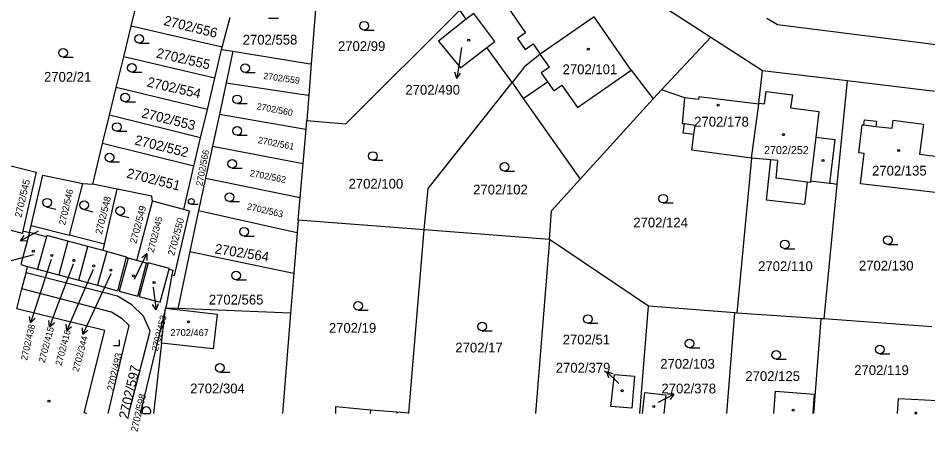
# Model space of a CAD drawing. Extents: x -496682 to -495776, y -1088797 to -1088018.
# Drawn here: x -496557.4 to -496399.5, y -1088572.6 to -1088500.7 of the extents above; entities that cross this region are included whole.
import ezdxf

# ---------------------------------------------------------------- set-up
doc = ezdxf.new("R2010")
doc.units = 0
for name, color, linetype in [('Hranice parcel', 7, 'Continuous'), ('Parcelní čísla', 7, 'Continuous'), ('Pop  PČ popisy', 7, 'Continuous'), ('Vnitřní kresba', 7, 'Continuous'), ('Značky budov', 7, 'Continuous'), ('Značky kultur', 7, 'Continuous')]:
    doc.layers.add(name, color=color, linetype=linetype)

msp = doc.modelspace()

# ---------------------------------------------------------------- linework, layer by layer
at = {"layer": 'Hranice parcel'}
for p, q in [((-496537.8, -1088502.11), (-496536.46, -1088496.6)), ((-496450.23, -1088495.49), (-496437.15, -1088504)), ((-496505.72, -1088498.45), (-496506.52, -1088508.66)), ((-496479.61, -1088500.91), (-496480.76, -1088499.32)), ((-496522.01, -1088505.76), (-496520.6, -1088500.55)), ((-496539.1, -1088507.43), (-496537.8, -1088502.11)), ((-496522.01, -1088505.76), (-496537.8, -1088502.11)), ((-496445.71, -1088513.16), (-496437.15, -1088504)), ((-496437.15, -1088504), (-496428.21, -1088509.82)), ((-496523.29, -1088511.13), (-496522.11, -1088506.13)), ((-496522.11, -1088506.13), (-496522.01, -1088505.76)), ((-496522.11, -1088506.13), (-496520.16, -1088506.45)), ((-496471.67, -1088511.91), (-496476.06, -1088505.83)), ((-496540.39, -1088512.75), (-496539.1, -1088507.43)), ((-496523.29, -1088511.13), (-496539.1, -1088507.43)), ((-496520.16, -1088506.45), (-496521.33, -1088511.93)), ((-496506.52, -1088508.66), (-496506.95, -1088514.12)), ((-496469.49, -1088509.17), (-496471.67, -1088511.91)), ((-496428.21, -1088509.82), (-496413.5, -1088511.53)), ((-496524.57, -1088516.56), (-496523.29, -1088511.13)), ((-496521.33, -1088511.93), (-496522.49, -1088517.38)), ((-496413.5, -1088511.53), (-496415.26, -1088529.6)), ((-496413.5, -1088511.53), (-496394.97, -1088513.78)), ((-496541.56, -1088517.57), (-496540.39, -1088512.75)), ((-496524.57, -1088516.56), (-496540.39, -1088512.75)), ((-496506.95, -1088514.12), (-496507.29, -1088518.51)), ((-496441.68, -1088514.55), (-496445.71, -1088513.16)), ((-496525.75, -1088521.53), (-496524.57, -1088516.56)), ((-496522.49, -1088517.38), (-496523.68, -1088522.94)), ((-496542.77, -1088522.52), (-496541.56, -1088517.57)), ((-496525.75, -1088521.53), (-496541.56, -1088517.57)), ((-496507.42, -1088520.02), (-496507.29, -1088518.51)), ((-496507.95, -1088525.99), (-496507.42, -1088520.02)), ((-496526.9, -1088526.44), (-496525.75, -1088521.53)), ((-496544.48, -1088529.55), (-496542.77, -1088522.52)), ((-496526.9, -1088526.44), (-496542.77, -1088522.52)), ((-496523.68, -1088522.94), (-496524.87, -1088528.52)), ((-496523.68, -1088522.94), (-496507.95, -1088525.99)), ((-496430.07, -1088525.02), (-496432.62, -1088551.99)), ((-496528.68, -1088533.96), (-496526.9, -1088526.44)), ((-496508.46, -1088531.91), (-496507.95, -1088525.99)), ((-496548.52, -1088538.44), (-496546.2, -1088529.44)), ((-496546.2, -1088529.44), (-496544.48, -1088529.55)), ((-496540.23, -1088530.42), (-496544.48, -1088529.55)), ((-496524.87, -1088528.52), (-496526.08, -1088534.17)), ((-496524.87, -1088528.52), (-496508.46, -1088531.91)), ((-496415.26, -1088529.6), (-496417.53, -1088552.98)), ((-496542.41, -1088540.01), (-496540.23, -1088530.42)), ((-496536.84, -1088542.85), (-496534.08, -1088532.5)), ((-496528.68, -1088533.96), (-496534.08, -1088532.5)), ((-496508.81, -1088535.85), (-496508.46, -1088531.91)), ((-496526.08, -1088534.17), (-496527.6, -1088541.29)), ((-496508.81, -1088535.85), (-496508.98, -1088537.97)), ((-496486.91, -1088537.52), (-496508.81, -1088535.85)), ((-496556.58, -1088537.69), (-496555.46, -1088537.96)), ((-496555.46, -1088537.96), (-496555.17, -1088536.73)), ((-496555.17, -1088536.73), (-496548.52, -1088538.44)), ((-496489.6, -1088569.29), (-496486.91, -1088537.52)), ((-496465.19, -1088539.18), (-496486.91, -1088537.52)), ((-496552.5, -1088538.74), (-496555.46, -1088537.96)), ((-496552.5, -1088538.74), (-496554.06, -1088544.33)), ((-496548.78, -1088539.48), (-496550.36, -1088545.33)), ((-496545.3, -1088540.41), (-496548.78, -1088539.48)), ((-496542.41, -1088540.01), (-496548.52, -1088538.44)), ((-496508.98, -1088537.97), (-496509.56, -1088545.05)), ((-496465.19, -1088539.18), (-496467.58, -1088569.45)), ((-496447.96, -1088550.78), (-496465.19, -1088539.18)), ((-496546.88, -1088546.28), (-496545.3, -1088540.41)), ((-496542.66, -1088541.12), (-496545.3, -1088540.41)), ((-496542.66, -1088541.12), (-496542.41, -1088540.01)), ((-496542.04, -1088541.29), (-496543.64, -1088547.15)), ((-496542.04, -1088541.29), (-496542.66, -1088541.12)), ((-496538.59, -1088542.23), (-496542.04, -1088541.29)), ((-496538.59, -1088542.23), (-496538.33, -1088542.45)), ((-496536.84, -1088542.85), (-496538.33, -1088542.45)), ((-496556.05, -1088544.98), (-496555.77, -1088543.87)), ((-496555.77, -1088543.87), (-496554.06, -1088544.33)), ((-496535.12, -1088543.32), (-496536.84, -1088542.85)), ((-496535.12, -1088543.32), (-496534.84, -1088543.23)), ((-496556.76, -1088547.74), (-496556.05, -1088544.98)), ((-496554.06, -1088544.33), (-496550.36, -1088545.33)), ((-496550.36, -1088545.33), (-496546.88, -1088546.28)), ((-496509.56, -1088545.05), (-496510.13, -1088551.97)), ((-496546.88, -1088546.28), (-496543.64, -1088547.15)), ((-496557.65, -1088551.23), (-496556.76, -1088547.74)), ((-496531.82, -1088551.13), (-496536.21, -1088569.45)), ((-496532.51, -1088557.18), (-496531.82, -1088551.13)), ((-496529.72, -1088551.21), (-496531.82, -1088551.13)), ((-496510.13, -1088551.97), (-496529.72, -1088551.21)), ((-496449.5, -1088569.45), (-496447.96, -1088550.78)), ((-496433, -1088551.96), (-496447.96, -1088550.78)), ((-496434.4, -1088569.45), (-496433, -1088551.96)), ((-496432.62, -1088551.99), (-496433, -1088551.96)), ((-496418.06, -1088552.96), (-496432.62, -1088551.99)), ((-496418.06, -1088552.96), (-496419.34, -1088569.45)), ((-496417.53, -1088552.98), (-496418.06, -1088552.96)), ((-496398.8, -1088554.34), (-496417.53, -1088552.98)), ((-496532.51, -1088557.18), (-496533.9, -1088569.45)), ((-496489.61, -1088569.45), (-496489.6, -1088569.29))]:
    msp.add_line(p, q, dxfattribs=at)
for points in [[(-496507.29, -1088518.51), (-496500.51, -1088519.07), (-496480.76, -1088499.32)], [(-496476.06, -1088505.83), (-496474.64, -1088504.74), (-496478.32, -1088499.89), (-496479.61, -1088500.91)], [(-496479.61, -1088500.91), (-496484.42, -1088504.69), (-496480.61, -1088509.32), (-496476.06, -1088505.83)], [(-496457.42, -1088500.49), (-496466.76, -1088506.96), (-496469.49, -1088509.17)], [(-496465.53, -1088511.75), (-496464.43, -1088513.34), (-496463.02, -1088512.35), (-496460.32, -1088516.24), (-496450.98, -1088509.77), (-496457.42, -1088500.49)], [(-496427.43, -1088500.69), (-496425.57, -1088501.8), (-496381.96, -1088507.33)], [(-496520.16, -1088506.45), (-496507.08, -1088508.57), (-496506.52, -1088508.66)], [(-496430.07, -1088525.02), (-496428.84, -1088515.66), (-496428.82, -1088515.46), (-496428.21, -1088509.82)], [(-496521.33, -1088511.93), (-496508.27, -1088513.92), (-496506.95, -1088514.12)], [(-496486.91, -1088537.52), (-496486.26, -1088530.32), (-496471.67, -1088511.91)], [(-496471.67, -1088511.91), (-496469.73, -1088514.66), (-496465.53, -1088511.75)], [(-496465.19, -1088539.18), (-496464.79, -1088534.19), (-496459.83, -1088528.71), (-496447.17, -1088514.73), (-496445.71, -1088513.16)], [(-496430.07, -1088525.02), (-496440.44, -1088523.65), (-496440.09, -1088520.95), (-496441.94, -1088520.7), (-496441.73, -1088519.1), (-496442.06, -1088519.05), (-496441.68, -1088514.55)], [(-496522.49, -1088517.38), (-496507.83, -1088519.95), (-496507.42, -1088520.02)], [(-496401.7, -1088530.59), (-496411.17, -1088529.49), (-496410.56, -1088524.24), (-496411.46, -1088524.14), (-496410.89, -1088519.24), (-496410.59, -1088519.28), (-496410.48, -1088518.4), (-496408.38, -1088518.63), (-496408.48, -1088519.52), (-496405.68, -1088519.85), (-496405.48, -1088518.47), (-496400.24, -1088519.14), (-496400.91, -1088524.37), (-496396.87, -1088524.88), (-496397.69, -1088531.06), (-496401.7, -1088530.59)], [(-496415.26, -1088529.6), (-496416.28, -1088529.48), (-496416.53, -1088529.45), (-496419.84, -1088529.05), (-496419.87, -1088529.29), (-496420.45, -1088529.21), (-496420.88, -1088533.09), (-496427.49, -1088532.36), (-496426.73, -1088525.36), (-496430.07, -1088525.02)], [(-496560.1, -1088526.02), (-496554.29, -1088527.46), (-496556.58, -1088537.69)], [(-496555.17, -1088536.73), (-496553.11, -1088528.01), (-496546.2, -1088529.44)], [(-496534.08, -1088532.5), (-496534.19, -1088531.67), (-496540.23, -1088530.42)], [(-496530.74, -1088545.34), (-496530.3, -1088545.43), (-496527.65, -1088534.24), (-496528.68, -1088533.96)], [(-496526.08, -1088534.17), (-496509.77, -1088537.79), (-496508.98, -1088537.97)], [(-496556.58, -1088537.69), (-496556.68, -1088538.12), (-496563.36, -1088536.35)], [(-496555.46, -1088537.96), (-496556.98, -1088543.54), (-496555.77, -1088543.87)], [(-496548.78, -1088539.48), (-496552.43, -1088538.5), (-496552.5, -1088538.74)], [(-496543.64, -1088547.15), (-496540.12, -1088548.11), (-496538.59, -1088542.23)], [(-496538.33, -1088542.45), (-496539.88, -1088548.17), (-496536.67, -1088549.04), (-496535.12, -1088543.32)], [(-496527.6, -1088541.29), (-496529.6, -1088550.65), (-496529.72, -1088551.21)], [(-496527.6, -1088541.29), (-496510.41, -1088544.87), (-496509.56, -1088545.05)], [(-496534.84, -1088543.23), (-496536.43, -1088549.11), (-496532.74, -1088550.1), (-496531.19, -1088544.37)], [(-496531.19, -1088544.37), (-496531.15, -1088544.22), (-496534.84, -1088543.23)], [(-496538.19, -1088569.45), (-496534.51, -1088555.13), (-496535.64, -1088552.52), (-496537.69, -1088550.53), (-496540.19, -1088549.03), (-496556.05, -1088544.98)], [(-496530.74, -1088545.34), (-496531.65, -1088550.49), (-496531.82, -1088551.13)], [(-496531.19, -1088544.37), (-496530.59, -1088544.52), (-496530.74, -1088545.34)], [(-496541.78, -1088569.45), (-496539.18, -1088558.45), (-496538.17, -1088554.12), (-496539.34, -1088553), (-496541.24, -1088551.8), (-496556.76, -1088547.74)], [(-496545.5, -1088569.45), (-496545.94, -1088569.34), (-496542.39, -1088555.02), (-496557.65, -1088551.23)], [(-496531.82, -1088551.13), (-496522.87, -1088552.14), (-496523.55, -1088558.19), (-496532.51, -1088557.18)], [(-496510.13, -1088551.97), (-496510.95, -1088562.22), (-496511.53, -1088569.45)], [(-496454.49, -1088568.22), (-496453.89, -1088562.66), (-496450.42, -1088562.94), (-496450.89, -1088568.53), (-496454.49, -1088568.22)], [(-496449.01, -1088569.45), (-496448.61, -1088565.79)], [(-496448.61, -1088565.79), (-496444.95, -1088566.18), (-496445.31, -1088569.45)], [(-496426.22, -1088569.45), (-496425.91, -1088565.54), (-496419.2, -1088566.07)], [(-496419.2, -1088566.07), (-496419.47, -1088569.45)], [(-496404.72, -1088569.45), (-496404.57, -1088566.8), (-496397.81, -1088567.16), (-496397.94, -1088569.45)], [(-496502.29, -1088569.45), (-496502.24, -1088568.24), (-496496.2, -1088568.8), (-496491.67, -1088569.13), (-496489.6, -1088569.29)]]:
    msp.add_lwpolyline(points, dxfattribs=at)
at = {"layer": 'Pop  PČ popisy'}
for p, q in [((-496480.45, -1088505.79), (-496480.81, -1088508.21)), ((-496480.81, -1088508.21), (-496481.23, -1088511.18)), ((-496481.23, -1088511.18), (-496481.58, -1088510.12)), ((-496481.23, -1088511.18), (-496480.59, -1088510.26)), ((-496553.95, -1088537.73), (-496554.37, -1088537.96)), ((-496554.37, -1088537.96), (-496556.99, -1088539.42)), ((-496556.99, -1088539.42), (-496556.36, -1088538.49)), ((-496556.99, -1088539.42), (-496555.88, -1088539.37)), ((-496555.81, -1088542.14), (-496558.71, -1088542.92)), ((-496554.8, -1088541.88), (-496555.81, -1088542.14)), ((-496551.67, -1088542.64), (-496554.34, -1088550.83)), ((-496536.4, -1088544.39), (-496535.08, -1088541.69)), ((-496535.08, -1088541.69), (-496535.97, -1088542.37)), ((-496535.08, -1088541.69), (-496535.07, -1088542.81)), ((-496547.89, -1088543.46), (-496550.92, -1088551.55)), ((-496544.42, -1088544.4), (-496547.82, -1088552.26)), ((-496541.33, -1088545.13), (-496544.92, -1088552.93)), ((-496537.2, -1088546.07), (-496536.4, -1088544.39)), ((-496533.98, -1088547.45), (-496533.85, -1088548.43)), ((-496533.85, -1088548.43), (-496533.43, -1088551.4)), ((-496533.43, -1088551.4), (-496534.07, -1088550.48)), ((-496533.43, -1088551.4), (-496533.08, -1088550.34)), ((-496554.34, -1088550.83), (-496555.27, -1088553.68)), ((-496550.92, -1088551.55), (-496551.95, -1088554.37)), ((-496555.27, -1088553.68), (-496555.43, -1088552.58)), ((-496555.27, -1088553.68), (-496554.48, -1088552.89)), ((-496551.95, -1088554.37), (-496552.07, -1088553.26)), ((-496551.95, -1088554.37), (-496551.13, -1088553.6)), ((-496547.82, -1088552.26), (-496548.99, -1088555.02)), ((-496544.92, -1088552.93), (-496546.19, -1088555.65)), ((-496548.99, -1088555.02), (-496549.06, -1088553.91)), ((-496548.99, -1088555.02), (-496548.14, -1088554.3)), ((-496546.19, -1088555.65), (-496546.22, -1088554.53)), ((-496546.19, -1088555.65), (-496545.31, -1088554.95)), ((-496453.14, -1088564.24), (-496455.26, -1088562.12)), ((-496455.26, -1088562.12), (-496454.2, -1088562.47)), ((-496455.26, -1088562.12), (-496454.91, -1088563.18)), ((-496446.22, -1088567.44), (-496443.55, -1088566.08)), ((-496443.55, -1088566.08), (-496444.67, -1088566.09)), ((-496443.55, -1088566.08), (-496444.21, -1088566.98))]:
    msp.add_line(p, q, dxfattribs=at)
at = {"layer": 'Vnitřní kresba'}
for p, q in [((-496472.82, -1088498.22), (-496469.32, -1088503.27)), ((-496469.32, -1088503.27), (-496470.71, -1088504.23)), ((-496470.71, -1088504.23), (-496469.38, -1088506.14)), ((-496469.38, -1088506.14), (-496467.99, -1088505.18)), ((-496467.99, -1088505.18), (-496466.76, -1088506.96)), ((-496465.19, -1088509.22), (-496466.76, -1088506.96)), ((-496465.19, -1088509.22), (-496466.6, -1088510.2)), ((-496466.6, -1088510.2), (-496465.53, -1088511.75)), ((-496450.98, -1088509.77), (-496447.17, -1088514.73)), ((-496427.81, -1088515.59), (-496427.55, -1088513.46)), ((-496427.55, -1088513.46), (-496422.99, -1088514.03)), ((-496422.99, -1088514.03), (-496423.3, -1088516.32)), ((-496469.73, -1088514.66), (-496459.83, -1088528.71)), ((-496439.28, -1088514.85), (-496441.68, -1088514.55)), ((-496439.23, -1088514.41), (-496439.28, -1088514.85)), ((-496428.84, -1088515.66), (-496439.23, -1088514.41)), ((-496428.82, -1088515.46), (-496427.81, -1088515.59)), ((-496423.3, -1088516.32), (-496418.38, -1088516.91)), ((-496418.38, -1088516.91), (-496418.92, -1088521.38)), ((-496439.87, -1088519.34), (-496441.73, -1088519.1)), ((-496440.09, -1088520.95), (-496439.87, -1088519.34)), ((-496410.59, -1088519.28), (-496408.48, -1088519.52)), ((-496418.92, -1088521.38), (-496419.84, -1088529.05)), ((-496496.25, -1088569.45), (-496496.2, -1088568.8)), ((-496491.67, -1088569.13), (-496491.7, -1088569.45))]:
    msp.add_line(p, q, dxfattribs=at)
for points in [[(-496418.92, -1088521.38), (-496415.65, -1088521.78), (-496416.53, -1088529.45)], [(-496420.45, -1088529.21), (-496425.81, -1088528.51), (-496425.52, -1088525.48), (-496426.73, -1088525.36)]]:
    msp.add_lwpolyline(points, dxfattribs=at)
at = {"layer": 'Značky budov'}
msp.add_line((-496401.73, -1088569.45), (-496401.38, -1088569.45), dxfattribs=at)
for centre in [(-496479.2, -1088504.52), (-496458.43, -1088506.09), (-496435.9, -1088515.82), (-496424.53, -1088520.96), (-496404.54, -1088523.72), (-496417.68, -1088525.45), (-496554.79, -1088541.21), (-496551.56, -1088541.96), (-496547.77, -1088542.81), (-496544.31, -1088543.77), (-496541.35, -1088544.51), (-496537.38, -1088545.49), (-496533.83, -1088546.65), (-496527.86, -1088553.5), (-496452.55, -1088565.47), (-496552.07, -1088567.27), (-496447.06, -1088568.22), (-496422.84, -1088568.87)]:
    msp.add_circle(centre, 0.175, dxfattribs=at)
msp.add_arc((-496401.56, -1088569.43), 0.175, 353.714, 186.286, dxfattribs=at)
at = {"layer": 'Značky kultur'}
for p, q in [((-496513.98, -1088500.71), (-496512.23, -1088500.71)), ((-496497.35, -1088502.77), (-496495.6, -1088502.77)), ((-496536.4, -1088505.06), (-496534.65, -1088505.06)), ((-496549.63, -1088507.48), (-496547.88, -1088507.48)), ((-496537.68, -1088510.1), (-496535.93, -1088510.1)), ((-496518.03, -1088510.16), (-496516.28, -1088510.16)), ((-496538.82, -1088515.27), (-496537.07, -1088515.27)), ((-496519.39, -1088515.57), (-496517.64, -1088515.57)), ((-496540.3, -1088520.38), (-496538.55, -1088520.38)), ((-496519.39, -1088521.07), (-496517.64, -1088521.07)), ((-496541.58, -1088525.69), (-496539.83, -1088525.69)), ((-496520.26, -1088526.8), (-496518.51, -1088526.8)), ((-496495.83, -1088525.42), (-496494.08, -1088525.42)), ((-496472.98, -1088527.29), (-496471.23, -1088527.29)), ((-496527.35, -1088533.07), (-496526.18, -1088533.07)), ((-496520.74, -1088532.6), (-496518.99, -1088532.6)), ((-496445.43, -1088532.84), (-496443.68, -1088532.84)), ((-496552.58, -1088533.51), (-496550.89, -1088533.94)), ((-496546.14, -1088533.94), (-496544.45, -1088534.36)), ((-496539.89, -1088534.93), (-496538.2, -1088535.35)), ((-496518.19, -1088538.58), (-496516.44, -1088538.58)), ((-496424.3, -1088540.78), (-496422.55, -1088540.78)), ((-496406.41, -1088540.04), (-496404.66, -1088540.04)), ((-496519.55, -1088546.21), (-496517.8, -1088546.21)), ((-496498.41, -1088551.48), (-496496.66, -1088551.48)), ((-496476.86, -1088555.07), (-496475.11, -1088555.07)), ((-496458.5, -1088553.76), (-496456.75, -1088553.76)), ((-496539.85, -1088557.64), (-496539.85, -1088556.64)), ((-496540.85, -1088557.64), (-496539.85, -1088557.64)), ((-496440.84, -1088558.01), (-496439.09, -1088558.01)), ((-496425.83, -1088559.98), (-496424.08, -1088559.98)), ((-496407.82, -1088559.04), (-496406.07, -1088559.04)), ((-496522.42, -1088562.26), (-496520.67, -1088562.26)), ((-496535.77, -1088569.45), (-496534.52, -1088569.45))]:
    msp.add_line(p, q, dxfattribs=at)
for centre, radius in [((-496497.35, -1088502.02), 0.75), ((-496536.4, -1088504.31), 0.75), ((-496549.63, -1088506.73), 0.75), ((-496537.68, -1088509.35), 0.75), ((-496518.03, -1088509.41), 0.75), ((-496538.82, -1088514.52), 0.75), ((-496519.39, -1088514.82), 0.75), ((-496540.3, -1088519.63), 0.75), ((-496519.39, -1088520.32), 0.75), ((-496541.58, -1088524.94), 0.75), ((-496495.83, -1088524.67), 0.75), ((-496520.26, -1088526.05), 0.75), ((-496472.98, -1088526.54), 0.75), ((-496520.74, -1088531.85), 0.75), ((-496445.43, -1088532.09), 0.75), ((-496552.4, -1088532.78), 0.75), ((-496545.96, -1088533.21), 0.75), ((-496527.36, -1088532.57), 0.502), ((-496539.71, -1088534.2), 0.75), ((-496518.19, -1088537.83), 0.75), ((-496424.3, -1088540.03), 0.75), ((-496406.41, -1088539.29), 0.75), ((-496519.55, -1088545.46), 0.75), ((-496498.41, -1088550.73), 0.75), ((-496476.86, -1088554.32), 0.75), ((-496458.5, -1088553.01), 0.75), ((-496440.84, -1088557.26), 0.75), ((-496407.82, -1088558.29), 0.75), ((-496425.83, -1088559.23), 0.75), ((-496522.42, -1088561.51), 0.75)]:
    msp.add_circle(centre, radius, dxfattribs=at)
msp.add_arc((-496535.14, -1088569.03), 0.75, 326.0818, 213.9182, dxfattribs=at)

# ---------------------------------------------------------------- texts
at = {"layer": 'Parcelní čísla'}
for s, height, rotation, p in [('2702/556', 1.7, 346, (-496532.26, -1088501.87)), ('2702/555', 1.7, 347, (-496533.54, -1088507.52)), ('2702/554', 1.7, 347, (-496535.15, -1088512.56)), ('2702/559', 1.139, 352, (-496514.9, -1088511.27)), ('2702/560', 1.139, 349, (-496516.09, -1088516.53)), ('2702/553', 1.7, 346, (-496536.09, -1088517.93)), ('2702/552', 1.7, 346, (-496537.3, -1088522.64)), ('2702/561', 1.139, 349, (-496515.85, -1088522.42)), ('2702/566', 1.139, 79, (-496525.45, -1088529.96)), ('2702/551', 1.7, 346, (-496538.71, -1088528.41)), ('2702/562', 1.139, 349, (-496517.28, -1088528.16)), ('2702/545', 1.2, 77, (-496556.86, -1088535.43)), ('2702/546', 1.139, 77, (-496549.27, -1088536.77)), ('2702/548', 1.2, 76, (-496542.9, -1088538.36)), ('2702/563', 1.139, 347, (-496517.76, -1088533.94)), ('2702/549', 1.2, 75, (-496536.9, -1088539.97)), ('2702/345', 1.139, 76, (-496533.89, -1088541.52)), ('2702/550', 1.2, 75, (-496530.32, -1088542.09)), ('2702/564', 1.7, 351, (-496523.37, -1088541.59)), ('2702/453', 1.139, 76, (-496533.17, -1088558.69)), ('2702/438', 1.139, 77, (-496555.89, -1088560.27)), ('2702/415', 1.139, 75, (-496552.82, -1088560.69)), ('2702/416', 1.139, 75, (-496549.91, -1088561.21)), ('2702/344', 1.139, 75, (-496546.94, -1088562.27)), ('2702/493', 1.2, 77, (-496540.87, -1088565.59)), ('2702/597', 1.7, 77, (-496538.33, -1088570.49)), ('2702/598', 1.2, 77, (-496536.72, -1088572.7))]:
    msp.add_text(s, height=height, rotation=rotation, dxfattribs=at).set_placement(p)
for s, height, p in [('2702/558', 1.7, (-496518.43, -1088505.3)), ('2702/99', 1.7, (-496501.89, -1088506.42)), ('2702/101', 1.7, (-496462.89, -1088510.45)), ('2702/21', 1.7, (-496552.93, -1088511.76)), ('2702/490', 1.7, (-496490.19, -1088514.01)), ('2702/178', 1.7, (-496440.04, -1088519.56)), ('2702/252', 1.394, (-496427.92, -1088524.34)), ('2702/135', 1.7, (-496409.16, -1088528.07)), ('2702/100', 1.7, (-496500.05, -1088530.34)), ('2702/102', 1.7, (-496478.42, -1088531.35)), ('2702/124', 1.7, (-496450.61, -1088537.08)), ('2702/110', 1.7, (-496428.94, -1088544.67)), ('2702/130', 1.7, (-496411.44, -1088544.58)), ('2702/565', 1.7, (-496524.32, -1088550.49)), ('2702/19', 1.7, (-496503.47, -1088555.4)), ('2702/467', 1.2, (-496530.99, -1088555.98)), ('2702/51', 1.7, (-496462.87, -1088557.43)), ('2702/17', 1.7, (-496481.51, -1088558.83)), ('2702/103', 1.7, (-496445.94, -1088561.65)), ('2702/379', 1.7, (-496464.08, -1088562.32)), ('2702/119', 1.7, (-496412.26, -1088562.75)), ('2702/125', 1.7, (-496431.16, -1088563.78)), ('2702/304', 1.7, (-496527.55, -1088565.93)), ('2702/378', 1.7, (-496445.73, -1088565.94))]:
    msp.add_text(s, height=height, dxfattribs=at).set_placement(p)

doc.saveas('drawing.dxf')
